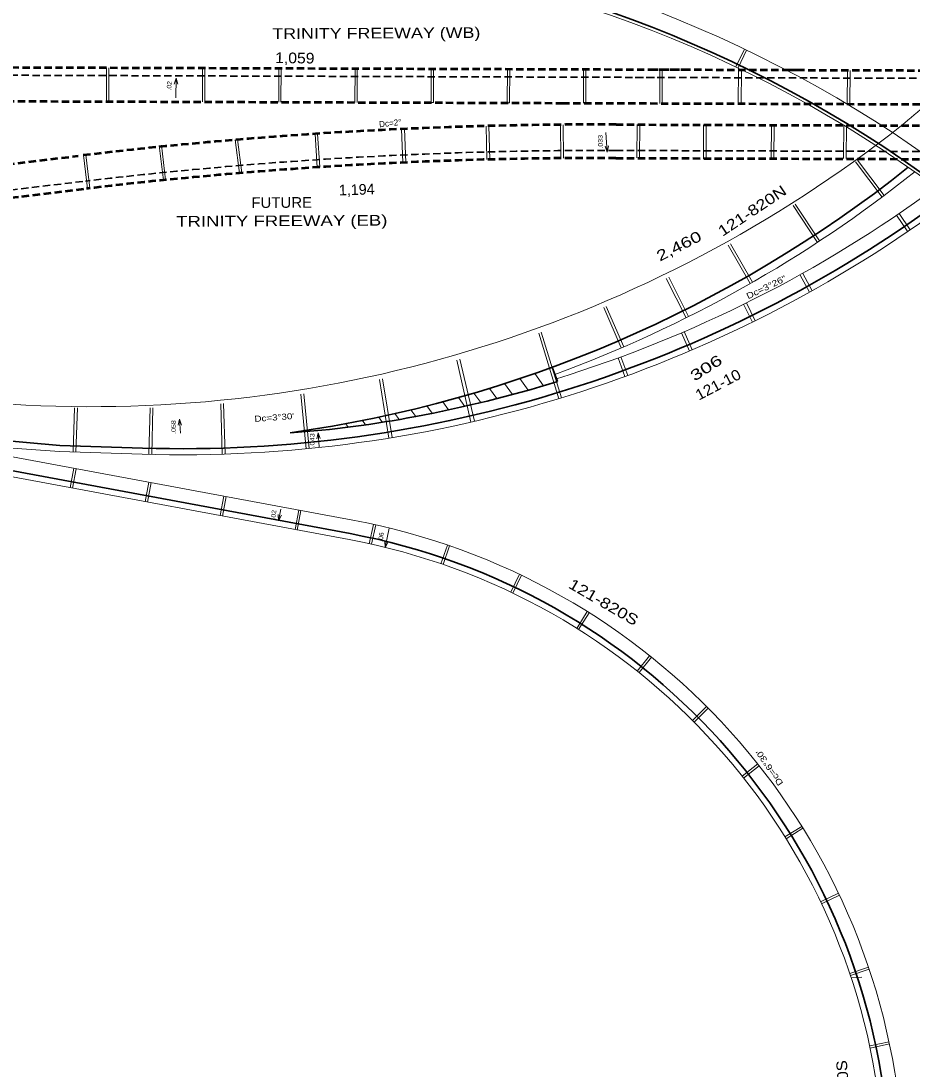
# Model space of a CAD drawing. Extents: x 2354993 to 2372084, y 6966390 to 6990057.
# Drawn here: x 2363006 to 2364175, y 6976742 to 6978118 of the extents above; entities that cross this region are included whole.
import ezdxf
from ezdxf.enums import TextEntityAlignment as Align

# ---------------------------------------------------------------- set-up
doc = ezdxf.new("R2010")
doc.units = 0
doc.header["$LTSCALE"] = 3.2
doc.linetypes.add('MEDIUM_DASHED', pattern=[4.5, 3, -1.5])
for name, color, linetype, lineweight in [('12', 7, 'Continuous', 13), ('13', 7, 'Continuous', 13), ('17', 7, 'Continuous', 13), ('19', 7, 'Continuous', 13), ('23', 7, 'Continuous', 13), ('5', 7, 'Continuous', 35), ('61', 7, 'Continuous', 13), ('7', 7, 'Continuous', 13)]:
    doc.layers.add(name, color=color, linetype=linetype, lineweight=lineweight)

msp = doc.modelspace()

# ---------------------------------------------------------------- linework, layer by layer
at = {"layer": '12'}
for p, q in [((2363943.892, 6978057.276), (2363955.166, 6978080.703)), ((2363946.596, 6978055.978), (2363957.869, 6978079.405)), ((2363117.932, 6978011.954), (2363118.08, 6978055.955)), ((2363120.931, 6978011.944), (2363121.079, 6978055.945)), ((2363244.03, 6978055.53), (2363243.881, 6978011.53)), ((2363247.029, 6978055.52), (2363246.881, 6978011.52)), ((2363344.03, 6978055.193), (2363343.881, 6978011.193)), ((2363347.029, 6978055.183), (2363346.88, 6978011.182)), ((2363444.028, 6978054.856), (2363443.88, 6978010.855)), ((2363447.028, 6978054.845), (2363446.879, 6978010.845)), ((2363544.028, 6978054.518), (2363543.88, 6978010.518)), ((2363547.027, 6978054.508), (2363546.879, 6978010.507)), ((2363644.027, 6978054.181), (2363643.878, 6978010.18)), ((2363647.026, 6978054.17), (2363646.878, 6978010.17)), ((2363743.878, 6978009.844), (2363744.027, 6978053.844)), ((2363747.026, 6978053.834), (2363744.027, 6978053.844)), ((2363746.877, 6978009.833), (2363747.026, 6978053.834)), ((2363844.027, 6978053.507), (2363843.878, 6978009.506)), ((2363847.026, 6978053.496), (2363846.877, 6978009.496)), ((2363947.025, 6978053.159), (2363946.876, 6978009.159)), ((2363951.025, 6978053.145), (2363950.876, 6978009.145)), ((2363546.879, 6978010.507), (2363543.88, 6978010.518)), ((2363643.878, 6978010.18), (2363646.878, 6978010.17)), ((2364046.876, 6978008.821), (2364043.877, 6978008.831)), ((2364154.496, 6977862.559), (2364169.167, 6977841.094)), ((2364157.799, 6977864.816), (2364172.47, 6977843.351)), ((2364028.251, 6977784.188), (2364040.203, 6977761.604)), ((2364031.787, 6977786.059), (2364043.738, 6977763.474)), ((2363957.495, 6977747.502), (2363969.04, 6977724.206)), ((2363953.911, 6977745.726), (2363965.456, 6977722.43)), ((2363872.441, 6977708.284), (2363882.716, 6977684.401)), ((2363876.115, 6977709.865), (2363886.39, 6977685.981)), ((2363789.168, 6977675.319), (2363798.086, 6977650.897)), ((2363792.926, 6977676.691), (2363801.844, 6977652.269))]:
    msp.add_line(p, q, dxfattribs=at)
at = {"layer": '17'}
for p, q in [((2363213.75, 6977595.134), (2363216.528, 6977587.302)), ((2363395.689, 6977577.258), (2363398.467, 6977569.426)), ((2363343.757, 6977461.575), (2363343.114, 6977469.86)), ((2363483.762, 6977426.498), (2363483.119, 6977434.783))]:
    msp.add_line(p, q, dxfattribs=at)
for points in [[(2363214.946, 6977576.421), (2363213.75, 6977595.134), (2363211.989, 6977587.01)], [(2363396.885, 6977558.545), (2363395.689, 6977577.258), (2363393.928, 6977569.134)], [(2363346.852, 6977476.819), (2363343.757, 6977461.575), (2363347.575, 6977468.951)], [(2363488.892, 6977451.764), (2363483.762, 6977426.498), (2363487.58, 6977433.874)]]:
    msp.add_lwpolyline(points, dxfattribs=at)
at = {"layer": '19'}
for p, q in [((2363209.28, 6978042.726), (2363211.427, 6978034.696)), ((2363774.866, 6977945.446), (2363772.047, 6977953.265))]:
    msp.add_line(p, q, dxfattribs=at)
for points in [[(2363208.858, 6978016.946), (2363209.28, 6978042.726), (2363206.875, 6978034.776)], [(2363773.102, 6977971.168), (2363774.866, 6977945.446), (2363776.589, 6977953.571)]]:
    msp.add_lwpolyline(points, dxfattribs=at)
at = {"layer": '23'}
msp.add_line((2364095.179, 6976861.879), (2364109.155, 6976862.696), dxfattribs=at)
at = {"layer": '5', "linetype": 'MEDIUM_DASHED', "lineweight": 53}
for p, q in [((2363881.241, 6978053.379), (2362958.761, 6978056.492)), ((2364028.375, 6978052.885), (2363826.78, 6978053.565)), ((2364725.162, 6978050.535), (2364010.427, 6978052.946)), ((2362958.612, 6978012.492), (2363716.295, 6978009.935)), ((2363715.928, 6978009.937), (2364096.849, 6978008.653)), ((2364089.244, 6978008.678), (2364762.775, 6978006.406)), ((2363786.467, 6977981.699), (2365246.775, 6977976.776)), ((2362801.702, 6977907.216), (2363080.587, 6977940.529)), ((2363786.319, 6977937.7), (2365246.626, 6977932.776)), ((2362806.918, 6977863.526), (2363091.58, 6977897.529))]:
    msp.add_line(p, q, dxfattribs=at)
at = {"layer": '5', "linetype": 'MEDIUM_DASHED'}
for p, q in [((2363836.954, 6978043.529), (2362958.726, 6978046.492)), ((2364037.424, 6978042.853), (2363803.238, 6978043.643)), ((2364727.772, 6978040.524), (2364029.265, 6978042.88)), ((2363786.352, 6977947.7), (2365246.66, 6977942.776)), ((2362805.732, 6977873.455), (2363090.394, 6977907.458))]:
    msp.add_line(p, q, dxfattribs=at)
at = {"layer": '5', "lineweight": 13}
for p, q in [((2363680.035, 6977654.95), (2363691.558, 6977638.881)), ((2363640.373, 6977641.618), (2363650.618, 6977627.332)), ((2363660.284, 6977648.172), (2363671.172, 6977632.99)), ((2363579.665, 6977623.315), (2363587.923, 6977611.799)), ((2363600.066, 6977629.186), (2363608.996, 6977616.733)), ((2363620.301, 6977635.288), (2363629.893, 6977621.912)), ((2363538.357, 6977612.279), (2363545.24, 6977602.681)), ((2363559.096, 6977617.678), (2363566.672, 6977607.113)), ((2363475.093, 6977597.54), (2363479.821, 6977590.946)), ((2363496.358, 6977602.206), (2363501.818, 6977594.592)), ((2363517.445, 6977607.12), (2363523.623, 6977598.505)), ((2363432.015, 6977588.971), (2363435.238, 6977584.476)), ((2363453.646, 6977593.127), (2363457.63, 6977587.572)), ((2363436.244, 6977436.841), (2362775.531, 6977559.85)), ((2362952.814, 6977559.66), (2363056.326, 6977552.462)), ((2363441.003, 6977462.402), (2362950.662, 6977553.691)), ((2363164.981, 6977549.073), (2363056.326, 6977552.462))]:
    msp.add_line(p, q, dxfattribs=at)
at = {"layer": '5'}
for p, q in [((2363702.768, 6977663.093), (2363709.649, 6977644.314)), ((2363056.715, 6977560.454), (2362953.628, 6977569.627)), ((2363437.708, 6977444.706), (2362776.995, 6977567.714)), ((2363165.231, 6977557.069), (2363056.715, 6977560.454))]:
    msp.add_line(p, q, dxfattribs=at)
at = {"layer": '5', "lineweight": 13}
for centre, radius, start, end in [((2363244.672, 6976597.082), 1645.014, 38.12295, 103.3303), ((2363244.672, 6976597.082), 1619.014, 38.12295, 103.3303), ((2363127.192, 6979233.99), 1625.022, 309.51957, 311.04051), ((2363097.562, 6979328.645), 1717.302, 266.49182, 308.27248), ((2363127.192, 6979233.99), 1683.022, 290.12282, 308.67239), ((2363217.727, 6979240.251), 1666, 287.12386, 306.40449), ((2363217.727, 6979240.251), 1692, 268.21361, 306.66787), ((2363278.934, 6976591.886), 885.473, 4.66908, 79.45368), ((2363278.934, 6976591.886), 859.473, 4.66908, 79.45368)]:
    msp.add_arc(centre, radius, start, end, dxfattribs=at)
at = {"layer": '5'}
for centre, radius, start, end in [((2363244.672, 6976597.082), 1623.014, 38.12295, 103.3303), ((2363127.192, 6979233.99), 1673.022, 277.96238, 308.55257), ((2363217.727, 6979240.251), 1684, 268.21361, 306.58945), ((2363215.437, 6979250.646), 1680.639, 280.56637, 287.10131), ((2363265.996, 6978936.147), 1362.225, 273.91247, 280.90154), ((2363278.934, 6976591.886), 867.473, 4.66908, 79.45368)]:
    msp.add_arc(centre, radius, start, end, dxfattribs=at)
at = {"layer": '5', "linetype": 'MEDIUM_DASHED', "lineweight": 53}
for radius in [5739.578, 5695.578]:
    msp.add_arc((2363767.116, 6972242.154), radius, 89.80682, 96.81171, dxfattribs=at)
at = {"layer": '5', "linetype": 'MEDIUM_DASHED'}
msp.add_arc((2363767.116, 6972242.154), 5705.578, 89.80682, 96.81171, dxfattribs=at)
at = {"layer": '61'}
for p, q in [((2364090.028, 6978052.677), (2364089.879, 6978008.658)), ((2364093.528, 6978052.666), (2364093.379, 6978008.646)), ((2363713.621, 6977981.484), (2363714.004, 6977937.486)), ((2363717.121, 6977981.514), (2363717.504, 6977937.516)), ((2363814.093, 6977981.606), (2363813.947, 6977938.091)), ((2363817.593, 6977981.595), (2363817.447, 6977938.079)), ((2363901.359, 6977981.312), (2363901.209, 6977936.808)), ((2363904.859, 6977981.3), (2363904.709, 6977936.797)), ((2363990.363, 6977981.289), (2363990.213, 6977937.012)), ((2363993.862, 6977981.277), (2363993.713, 6977937)), ((2363394.559, 6977925.534), (2363391.681, 6977969.44)), ((2363397.837, 6977925.748), (2363394.985, 6977969.656)), ((2363506.94, 6977931.787), (2363504.93, 6977975.741)), ((2363510.86, 6977931.964), (2363508.88, 6977975.92)), ((2363617.208, 6977935.759), (2363616.05, 6977979.744)), ((2363620.771, 6977935.852), (2363619.64, 6977979.837)), ((2364085.307, 6977980.692), (2364085.159, 6977936.968)), ((2364088.807, 6977980.68), (2364088.659, 6977936.957)), ((2363192.564, 6977908.679), (2363187.108, 6977954.356)), ((2363195.55, 6977908.98), (2363190.087, 6977954.711)), ((2363292.347, 6977917.91), (2363286.922, 6977961.609)), ((2363295.34, 6977918.159), (2363289.913, 6977961.86)), ((2363093.163, 6977897.717), (2363087.932, 6977941.511)), ((2363096.142, 6977898.072), (2363090.911, 6977941.866)), ((2364100.733, 6977932.869), (2364135.48, 6977886.429)), ((2364103.535, 6977934.966), (2364138.28, 6977888.529)), ((2364018.816, 6977875.423), (2364050.64, 6977826.933)), ((2364021.742, 6977877.343), (2364053.564, 6977828.856)), ((2363933.77, 6977823.27), (2363962.558, 6977772.919)), ((2363936.808, 6977825.007), (2363965.595, 6977774.659)), ((2363852.499, 6977779.81), (2363878.497, 6977727.967)), ((2363855.628, 6977781.379), (2363881.627, 6977729.533)), ((2363770.355, 6977741.659), (2363793.423, 6977688.448)), ((2363773.566, 6977743.051), (2363796.636, 6977689.837)), ((2363711.411, 6977621.871), (2363685.022, 6977707.712)), ((2363714.929, 6977622.952), (2363688.481, 6977708.981)), ((2363596.2, 6977591.123), (2363577.5, 6977672.606)), ((2363600.62, 6977592.144), (2363581.647, 6977673.808)), ((2363488.545, 6977570.065), (2363476.092, 6977646.865)), ((2363492.823, 6977570.764), (2363480.136, 6977647.759)), ((2363380.001, 6977556.05), (2363373.1, 6977627.681)), ((2363383.787, 6977556.419), (2363376.704, 6977628.237)), ((2363074.252, 6977551.903), (2363076.056, 6977609.772)), ((2363077.93, 6977551.788), (2363079.735, 6977609.661)), ((2363173.608, 6977548.826), (2363175.196, 6977609.677)), ((2363177.287, 6977548.73), (2363178.88, 6977609.79)), ((2363269.927, 6977549.056), (2363267.89, 6977615.07)), ((2363273.606, 6977549.17), (2363271.561, 6977615.393)), ((2363075.204, 6977530.505), (2363070.445, 6977504.944)), ((2363078.153, 6977529.955), (2363073.395, 6977504.395)), ((2363173.515, 6977512.202), (2363168.756, 6977486.641)), ((2363176.464, 6977511.652), (2363171.705, 6977486.092)), ((2363271.826, 6977493.898), (2363267.067, 6977468.338)), ((2363274.775, 6977493.349), (2363270.016, 6977467.789)), ((2363370.136, 6977475.595), (2363365.377, 6977450.035)), ((2363373.086, 6977475.046), (2363368.327, 6977449.486)), ((2363468.322, 6977456.869), (2363462.761, 6977431.471)), ((2363471.253, 6977456.228), (2363465.691, 6977430.824)), ((2363565.242, 6977429.795), (2363556.836, 6977405.192)), ((2363568.081, 6977428.825), (2363559.673, 6977404.217)), ((2363659.659, 6977391.331), (2363648.479, 6977367.857)), ((2363662.367, 6977390.041), (2363651.186, 6977366.563)), ((2363748.816, 6977342.408), (2363734.942, 6977320.413)), ((2363751.354, 6977340.808), (2363737.482, 6977318.817)), ((2363830.586, 6977284.528), (2363814.316, 6977264.241)), ((2363832.926, 6977282.651), (2363816.659, 6977262.368)), ((2363905.215, 6977217.854), (2363886.826, 6977199.474)), ((2363907.336, 6977215.732), (2363888.943, 6977197.348)), ((2363972.477, 6977142.405), (2363952.054, 6977126.307)), ((2363974.334, 6977140.049), (2363953.915, 6977123.954)), ((2364030.243, 6977060.509), (2364008.132, 6977046.821)), ((2364031.822, 6977057.958), (2364009.715, 6977044.273)), ((2364078.323, 6976972.741), (2364054.808, 6976961.635)), ((2364079.604, 6976970.028), (2364056.094, 6976958.925)), ((2364117.693, 6976875.712), (2364093.298, 6976867.549)), ((2364118.644, 6976872.867), (2364094.25, 6976864.704)), ((2364144.668, 6976777.834), (2364119.327, 6976772.48)), ((2364145.289, 6976774.898), (2364119.947, 6976769.545))]:
    msp.add_line(p, q, dxfattribs=at)

# ---------------------------------------------------------------- texts
at = {"layer": '13'}
for s, width, p in [('TRINITY FREEWAY (WB)', 1.25, (2363472.031, 6978094.727)), ('FUTURE', 1.05, (2363347.915, 6977872.36)), ('TRINITY FREEWAY (EB)', 1.3, (2363348.042, 6977848.361))]:
    msp.add_text(s, height=14, rotation=0.302, dxfattribs=dict(at, width=width)).set_placement(p, align=Align.CENTER)
for s, rotation, width, p in [('1,059', 359.244, 1.1, (2363339.209, 6978062.444)), ('121-820N', 33.735, 1.25, (2363926.23, 6977834.217)), ('2,460', 26.958, 1.35, (2363843.998, 6977801.699)), ('306', 32.958, 1.45, (2363889.516, 6977644.174)), ('121-10', 27.735, 1.1, (2363895.257, 6977619.276)), ('121-820S', 329.864, 1.25, (2363722.888, 6977374.271)), ('121-820S', 94.338, 1.15, (2364096.276, 6976660.824))]:
    msp.add_text(s, height=14, rotation=rotation, dxfattribs=dict(at, width=width)).set_placement(p)
msp.add_text('1,194', height=14, rotation=1.924, dxfattribs=at).set_placement((2363423.094, 6977888.59))
at = {"layer": '17'}
msp.add_text('Dc=2°', height=8, rotation=6.166, dxfattribs=at).set_placement((2363476.026, 6977978.017))
for s, height, rotation, width, p in [("Dc=3°30'", 7.999, 4.213, 1.2, (2363312.426, 6977591.343)), ('.058', 6, 89.81, 1.15, (2363208.875, 6977575.605)), ('.043', 6, 89.81, 1.2, (2363390.813, 6977557.729)), ('.02', 5.999, 83.33, 1.1, (2363339.446, 6977463.122)), ('.06', 5.999, 83.33, 1.1, (2363480.477, 6977433.853)), ("Dc=6°30'", 7.999, 124.053, 1.25, (2364006.248, 6977117.193))]:
    msp.add_text(s, height=height, rotation=rotation, dxfattribs=dict(at, width=width)).set_placement(p)
at = {"layer": '19'}
for s, rotation, width, p in [('.02', 85.853, 1.1, (2363202.789, 6978026.231)), ('.033', 90.548, 1.15, (2363769.037, 6977950.136))]:
    msp.add_text(s, height=6, rotation=rotation, dxfattribs=dict(at, width=width)).set_placement(p)
at = {"layer": '7', "width": 1.25}
msp.add_text('Dc=3°26"', height=8, rotation=25.846, dxfattribs=at).set_placement((2363959.887, 6977752.301))

doc.saveas('drawing.dxf')
